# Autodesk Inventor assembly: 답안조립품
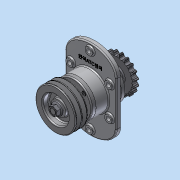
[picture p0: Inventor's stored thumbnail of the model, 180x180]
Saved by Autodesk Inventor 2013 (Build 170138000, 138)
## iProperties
Created: 2015-02
Part Number: 답안조립품
Document SubType Name: Assembly
Designer: dgall
Author: dgall
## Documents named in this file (12)
- C:\Users\dgall\Desktop\450207V1027\답안조립품.iam
- C:\Users\dgall\Desktop\450207V1027\1-본체.ipt
- C:\Users\dgall\Desktop\450207V1027\2-커버.ipt
- C:\Users\dgall\Desktop\450207V1027\3-축.ipt
- C:\Users\dgall\Desktop\450207V1027\4-V벨트풀리.ipt
- C:\Users\dgall\Desktop\450207V1027\5-체인 스프로킷.ipt
- C:\Users\dgall\Desktop\450207V1027\6-베어링 6206.ipt
- C:\Users\dgall\Desktop\450207V1027\7-부시.ipt
- C:\Users\dgall\Desktop\450207V1027\8-오일실 30x42.ipt
- C:\Users\dgall\Desktop\450207V1027\9-M16-너트.ipt
- C:\Users\dgall\Desktop\450207V1027\11-키 6x6.ipt
- C:\Users\dgall\Desktop\450207V1027\10-M6.ipt
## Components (23 placed, 11 different names)
1. 1-본체:1
2. 2-커버:1
3. 2-커버:2
4. 3-축:1
5. 4-V벨트풀리:1
6. 5-체인 스프로킷:1
7. 6-베어링 6206:1
8. 6-베어링 6206:2
9. 7-부시:1
10. 8-8-오일실 30x42:1
11. 8-8-오일실 30x42:2
12. 9-M16 너트:1
13. 9-M16 너트:2
14. 11-키 6x6:1
15. 11-키 6x6:2
16. 10-M6:1
17. 10-M6:2
18. 10-M6:3
19. 10-M6:4
20. 10-M6:5
21. 10-M6:6
22. 10-M6:7
23. 10-M6:8
